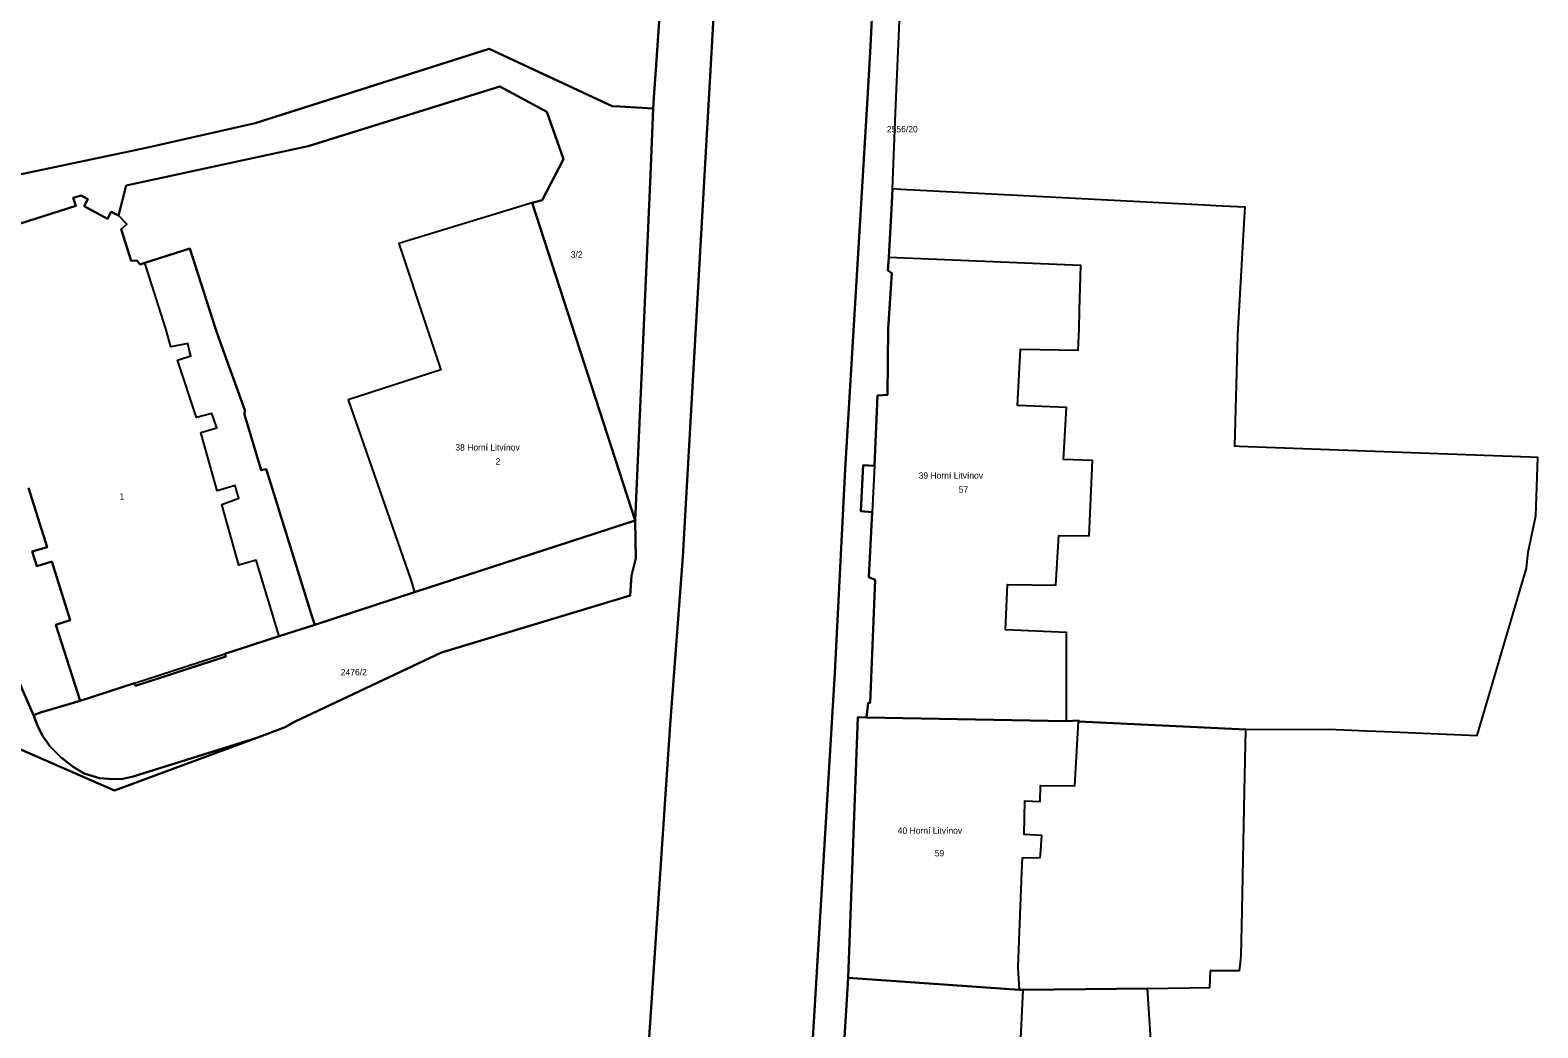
# Model space of a CAD drawing. Extents: x -792094 to -791524, y -979074 to -977761.
# Drawn here: x -791642.5 to -791524.2, y -978554.8 to -978476.6 of the extents above; entities that cross this region are included whole.
import ezdxf

# ---------------------------------------------------------------- set-up
doc = ezdxf.new("R2010")
doc.units = 0
doc.layers.add('katastr', color=7, linetype='Continuous')

msp = doc.modelspace()

# ---------------------------------------------------------------- linework, layer by layer
at = {"layer": 'katastr'}
for points in [[(-791618.69, -978324.45), (-791615.98, -978342.25), (-791615.16, -978345.63), (-791612.47, -978352.63), (-791601.26, -978386.52), (-791595.15, -978404.57), (-791589.17, -978422.12), (-791587.08, -978434.12), (-791587.15, -978444.99), (-791588.39, -978467.18), (-791589.13, -978480.19), (-791589.23, -978481.99), (-791591.27, -978517.9), (-791592.27, -978531.06), (-791594.51, -978564.55)], [(-791582.39, -978577.38), (-791579.36, -978527), (-791578.54, -978511), (-791576.81, -978482.36), (-791576.71, -978480.56), (-791576.57, -978478.3), (-791574.45, -978435.47), (-791575.29, -978425.51), (-791580.09, -978408.85), (-791579.08, -978407.45), (-791581.64, -978399.4), (-791583.52, -978398.39), (-791597.01, -978358.57), (-791608.04, -978325.55)], [(-791656.09, -978490.59), (-791634.23, -978485.99), (-791633.13, -978485.75), (-791624.82, -978483.87), (-791606.46, -978478.05), (-791596.81, -978482.53), (-791596.21, -978482.56), (-791594.91, -978482.64), (-791593.6, -978482.71), (-791593.54, -978481.86), (-791593.42, -978480.06), (-791592.23, -978462.56), (-791591.34, -978440.18), (-791591.4, -978436.47), (-791591.88, -978431.94), (-791592.54, -978426.66), (-791593.89, -978421.05), (-791595.95, -978413.98), (-791600.01, -978402.2)], [(-791600.01, -978402.2), (-791595.95, -978413.98), (-791593.89, -978421.05), (-791592.54, -978426.66), (-791591.88, -978431.94), (-791591.4, -978436.47), (-791591.34, -978440.18), (-791592.23, -978462.56), (-791593.42, -978480.06), (-791593.54, -978481.86), (-791593.6, -978482.71), (-791593.82, -978487.91), (-791595.02, -978515.05), (-791594.96, -978518.03), (-791595.31, -978519.34), (-791595.41, -978520.93), (-791610.21, -978525.39), (-791621.69, -978530.81), (-791622.47, -978531.26), (-791624.69, -978532.08), (-791635.85, -978536.21), (-791644.78, -978532.31)], [(-791594.51, -978564.55), (-791592.27, -978531.06), (-791591.27, -978517.9), (-791589.23, -978481.99), (-791589.13, -978480.19), (-791588.39, -978467.18), (-791587.15, -978444.99), (-791587.08, -978434.12), (-791589.17, -978422.12), (-791595.15, -978404.57)], [(-791574.45, -978435.47), (-791576.57, -978478.3), (-791576.71, -978480.56), (-791576.81, -978482.36), (-791578.54, -978511), (-791579.36, -978527), (-791582.39, -978577.38)], [(-791579.21, -978565.85), (-791578.3, -978550.91), (-791577.55, -978530.47), (-791576.86, -978530.48), (-791576.75, -978529.34), (-791576.58, -978529.34), (-791576.2, -978519.7), (-791576.69, -978519.49), (-791576.42, -978514.39), (-791577.32, -978514.31), (-791577.13, -978510.71), (-791576.25, -978510.76), (-791576.01, -978505.23), (-791575.21, -978505.19), (-791575.17, -978500), (-791574.87, -978495.64), (-791575.19, -978495.42), (-791575.13, -978494.4), (-791574.88, -978490.13), (-791574.84, -978489.02), (-791574.56, -978482.43), (-791574.48, -978480.63), (-791573.94, -978468.02)], [(-791645.14, -978492.33), (-791638.89, -978490.35), (-791639.09, -978489.73), (-791638.48, -978489.54), (-791637.94, -978489.84), (-791638.23, -978490.38), (-791636.4, -978491.37), (-791636.11, -978490.82), (-791635.55, -978491.12), (-791634.95, -978488.77), (-791620.67, -978485.67), (-791605.62, -978481), (-791601.94, -978482.99), (-791600.64, -978486.7), (-791602.3, -978489.9), (-791603.1, -978490.13), (-791595.02, -978515.05), (-791593.82, -978487.91), (-791593.6, -978482.71), (-791594.91, -978482.64), (-791596.21, -978482.56), (-791596.81, -978482.53), (-791606.46, -978478.05), (-791624.82, -978483.87), (-791633.13, -978485.75), (-791634.23, -978485.99), (-791656.09, -978490.59)], [(-791642.6, -978512.48), (-791641.14, -978517.12), (-791642.32, -978517.48), (-791641.95, -978518.62), (-791640.78, -978518.25), (-791639.33, -978522.86), (-791640.46, -978523.22), (-791638.54, -978529.19), (-791634.29, -978527.81), (-791627.2, -978525.5), (-791622.95, -978524.12), (-791624.74, -978518.14), (-791626.09, -978518.53), (-791627.43, -978513.79), (-791626.09, -978513.29), (-791626.3, -978512.61), (-791626.4, -978512.29), (-791627.79, -978512.72), (-791629.09, -978508.14), (-791627.82, -978507.78), (-791628.04, -978507.16), (-791628.22, -978506.65), (-791629.43, -978506.97), (-791630.91, -978502.47), (-791629.88, -978502.12), (-791629.97, -978501.75), (-791630.11, -978501.14), (-791631.44, -978501.41), (-791631.84, -978500), (-791633.48, -978494.83), (-791633.85, -978494.95), (-791634.11, -978494.64), (-791634.54, -978494.67), (-791635.34, -978492.19), (-791634.88, -978491.78), (-791635.55, -978491.12), (-791636.11, -978490.82), (-791636.4, -978491.37), (-791638.23, -978490.38), (-791637.94, -978489.84), (-791638.48, -978489.54), (-791639.09, -978489.73), (-791638.89, -978490.35), (-791645.14, -978492.33)], [(-791642.6, -978512.48), (-791641.14, -978517.12), (-791642.32, -978517.48), (-791641.95, -978518.62), (-791640.78, -978518.25), (-791639.33, -978522.86), (-791640.46, -978523.22), (-791638.54, -978529.19), (-791634.29, -978527.81), (-791634.22, -978528.01), (-791627.13, -978525.71), (-791627.2, -978525.5), (-791622.95, -978524.12), (-791620.15, -978523.21), (-791620.42, -978522.35), (-791623.7, -978511.83), (-791623.95, -978511.01), (-791624.34, -978511.1), (-791625.65, -978506.71), (-791625.63, -978506.38), (-791627.53, -978501.11), (-791627.94, -978499.98), (-791629.95, -978493.7), (-791633.48, -978494.83), (-791633.85, -978494.95), (-791634.11, -978494.64), (-791634.54, -978494.67), (-791635.34, -978492.19), (-791634.88, -978491.78), (-791635.55, -978491.12), (-791636.11, -978490.82), (-791636.4, -978491.37), (-791638.23, -978490.38), (-791637.94, -978489.84), (-791638.48, -978489.54), (-791639.09, -978489.73), (-791638.89, -978490.35), (-791645.14, -978492.33)], [(-791648.19, -978516.61), (-791642.22, -978530.31), (-791641.65, -978530.1), (-791638.54, -978529.19), (-791640.46, -978523.22), (-791639.33, -978522.86), (-791640.78, -978518.25), (-791641.95, -978518.62), (-791642.32, -978517.48), (-791641.14, -978517.12), (-791642.6, -978512.48)], [(-791644.78, -978532.31), (-791635.85, -978536.21), (-791624.69, -978532.08), (-791634.4, -978535.11), (-791635.21, -978535.31), (-791635.99, -978535.34), (-791637.02, -978535.25), (-791638.24, -978534.88), (-791639.09, -978534.37), (-791640.05, -978533.64), (-791640.94, -978532.73), (-791641.52, -978531.88), (-791641.89, -978531.12), (-791642.22, -978530.31), (-791648.19, -978516.61)]]:
    msp.add_lwpolyline(points, dxfattribs=at)
for points in [[(-791612.33, -978520.67), (-791595.02, -978515.05), (-791603.1, -978490.13), (-791602.3, -978489.9), (-791600.64, -978486.7), (-791601.94, -978482.99), (-791605.62, -978481), (-791620.67, -978485.67), (-791634.95, -978488.77), (-791635.55, -978491.12), (-791634.88, -978491.78), (-791635.34, -978492.19), (-791634.54, -978494.67), (-791634.11, -978494.64), (-791633.85, -978494.95), (-791633.48, -978494.83), (-791629.95, -978493.7), (-791627.94, -978499.98), (-791627.53, -978501.11), (-791625.63, -978506.38), (-791625.65, -978506.71), (-791624.34, -978511.1), (-791623.95, -978511.01), (-791623.7, -978511.83), (-791620.42, -978522.35), (-791620.15, -978523.21)], [(-791575.19, -978495.42), (-791574.87, -978495.64), (-791575.17, -978500), (-791575.21, -978505.19), (-791576.01, -978505.23), (-791576.25, -978510.76), (-791577.13, -978510.71), (-791577.32, -978514.31), (-791576.42, -978514.39), (-791576.69, -978519.49), (-791576.2, -978519.7), (-791576.58, -978529.34), (-791576.75, -978529.34), (-791576.86, -978530.48), (-791561.18, -978530.77), (-791560.21, -978530.73), (-791560.23, -978530.8), (-791547.12, -978531.43), (-791540.62, -978531.42), (-791537.63, -978531.54), (-791536.23, -978531.6), (-791528.98, -978531.9), (-791525.11, -978518.78), (-791524.97, -978517.53), (-791524.37, -978514.68), (-791524.21, -978510.1), (-791524.82, -978510.08), (-791535.61, -978509.67), (-791537, -978509.62), (-791547.63, -978509.22), (-791547.98, -978509.21), (-791547.73, -978500.52), (-791547.72, -978500), (-791547.67, -978499.12), (-791547.22, -978491.26), (-791547.18, -978490.47), (-791548.97, -978490.38), (-791550.37, -978490.3), (-791574.18, -978489.06), (-791574.84, -978489.02), (-791574.88, -978490.13), (-791575.13, -978494.4)], [(-791611.32, -978500), (-791610.27, -978503.22), (-791617.54, -978505.58), (-791612.62, -978519.69), (-791612.33, -978520.67), (-791595.02, -978515.05), (-791603.1, -978490.13), (-791613.54, -978493.3)], [(-791576.2, -978519.7), (-791576.58, -978529.34), (-791576.75, -978529.34), (-791576.86, -978530.48), (-791561.18, -978530.77), (-791561.17, -978524.24), (-791561.17, -978523.83), (-791565.97, -978523.61), (-791565.8, -978520.07), (-791562.02, -978520.12), (-791561.78, -978516.22), (-791559.41, -978516.23), (-791559.14, -978510.33), (-791561.43, -978510.25), (-791561.17, -978506.18), (-791565.03, -978506.02), (-791564.8, -978501.6), (-791560.26, -978501.68), (-791560.2, -978500), (-791560.16, -978498.53), (-791560.07, -978495.03), (-791575.13, -978494.4), (-791575.19, -978495.42), (-791574.87, -978495.64), (-791575.17, -978500), (-791575.21, -978505.19), (-791576.01, -978505.23), (-791576.25, -978510.76), (-791576.42, -978514.39), (-791576.69, -978519.49)], [(-791595.41, -978520.93), (-791595.31, -978519.34), (-791594.96, -978518.03), (-791595.02, -978515.05), (-791612.33, -978520.67), (-791620.15, -978523.21), (-791622.95, -978524.12), (-791627.2, -978525.5), (-791627.13, -978525.71), (-791634.22, -978528.01), (-791634.29, -978527.81), (-791638.54, -978529.19), (-791641.65, -978530.1), (-791642.22, -978530.31), (-791641.89, -978531.12), (-791641.52, -978531.88), (-791640.94, -978532.73), (-791640.05, -978533.64), (-791639.09, -978534.37), (-791638.24, -978534.88), (-791637.02, -978535.25), (-791635.99, -978535.34), (-791635.21, -978535.31), (-791634.4, -978535.11), (-791624.69, -978532.08), (-791622.47, -978531.26), (-791621.69, -978530.81), (-791610.21, -978525.39)], [(-791577.55, -978530.47), (-791578.3, -978550.91), (-791564.87, -978551.85), (-791564.97, -978550.1), (-791564.94, -978549.35), (-791564.68, -978542.63), (-791564.64, -978541.49), (-791563.25, -978541.48), (-791563.23, -978541.26), (-791563.12, -978539.74), (-791564.51, -978539.67), (-791564.45, -978537.02), (-791563.25, -978537.07), (-791563.22, -978535.83), (-791560.52, -978535.86), (-791560.23, -978530.8), (-791560.21, -978530.73), (-791561.18, -978530.77), (-791576.86, -978530.48)], [(-791547.22, -978536.28), (-791547.12, -978531.43), (-791560.23, -978530.8), (-791560.21, -978530.73), (-791561.18, -978530.77), (-791576.86, -978530.48), (-791577.55, -978530.47), (-791578.3, -978550.91), (-791564.87, -978551.85), (-791564.58, -978551.85), (-791554.82, -978551.74), (-791549.95, -978551.68), (-791549.89, -978550.35), (-791547.61, -978550.35), (-791547.57, -978549.96), (-791547.49, -978549.15), (-791547.44, -978546.87), (-791547.36, -978542.99), (-791547.33, -978541.59)], [(-791578.3, -978550.91), (-791579.21, -978565.85), (-791569.52, -978566.26), (-791565.24, -978565.51), (-791564.58, -978551.85), (-791564.87, -978551.85)], [(-791565.24, -978565.51), (-791558.17, -978563.43), (-791554.13, -978562.57), (-791554.82, -978551.74), (-791564.58, -978551.85), (-791564.87, -978551.85), (-791578.3, -978550.91), (-791579.21, -978565.85), (-791569.52, -978566.26)]]:
    msp.add_lwpolyline(points, close=True, dxfattribs=at)

# ---------------------------------------------------------------- texts
for s, p in [('2556/20', (-791575.27, -978484.59)), ('3/2', (-791600.07, -978494.42)), ('38 Horní Litvínov', (-791609.12, -978509.55)), ('2', (-791605.96, -978510.65)), ('39 Horní Litvínov', (-791572.78, -978511.76)), ('1', (-791635.46, -978513.41)), ('57', (-791569.64, -978512.86)), ('2476/2', (-791618.11, -978527.19)), ('40 Horní Litvínov', (-791574.42, -978539.61)), ('59', (-791571.52, -978541.39))]:
    msp.add_text(s, height=0.5, dxfattribs=at).set_placement(p)

doc.saveas('drawing.dxf')
